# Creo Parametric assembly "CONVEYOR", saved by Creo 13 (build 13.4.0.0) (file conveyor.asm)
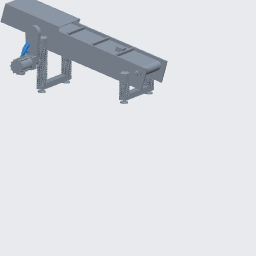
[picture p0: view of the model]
Units: millimeter Newton Second (mmNs); MM, TONNE, SECS

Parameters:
  MC_INTF = "10/28/2026 301"

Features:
  1. datum plane "ASM_RIGHT"
  2. datum plane "ASM_TOP"
  3. datum plane "ASM_FRONT"
  4. coordinate system
  5. component "SIDE_PLATE"
  6. component "SIDE_PLATE"
  7. component "IDLER_ROLLER"
  8. component "DRIVER_ROLLER"
  9. component "CARRIER_ROLLER"
  10. component "CARRIER_ROLLER"
  11. component "CARRIER_ROLLER"
  12. component "BELT"
  13. component "FLANGE_BEARING"
  14. component "FLANGE_BEARING"
  15. component "FLANGE_BEARING"
  16. component "FLANGE_BEARING"
  17. datum plane "ADTM2"
  18. component "LEG_LOW"
  19. datum plane "ADTM3"
  20. component "LEG_LOW"
  21. datum plane "ADTM4"
  22. component "LEG_HIGH"
  23. datum plane "ADTM5"
  24. component "LEG_HIGH"
  25. component "LEVELLING_FOOT"
  26. component "LEVELLING_FOOT"
  27. component "LEVELLING_FOOT"
  28. component "LEVELLING_FOOT"
  29. component "CROSS_BAR"
  30. component "PULLEY_LARGE"
  31. component "DRIVE_BELT"
  32. component "PULLEY_SMALL"
  33. component "MOTOR"
  34. component "BELT_GUARD"
  35. component "CROSS_BAR"
  36. component "MOTOR_BRACKET"
  37. component "BOLT_LEG"
  38. component "BOLT_LEG"
  39. component "BOLT_LEG"
  40. component "BOLT_LEG"
  41. component "BOLT_LEG"
  42. component "BOLT_LEG"
  43. component "BOLT_LEG"
  44. component "BOLT_LEG"
  45. datum axis
  46. component "CLEAT_SET"
  47. component
  48. component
